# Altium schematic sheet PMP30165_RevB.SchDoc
size 431 x 279 mm; Date: Not shown in title block; ApprovedBy: Not shown in title block; CheckedBy: Not shown in title block; Author: Not shown in title block; CompanyName: Not shown in title block; Engineer: Not shown in title block; Organization: Not shown in title block; Address1: Not shown in title block; Address2: Not shown in title block; Address3: Not shown in title block; Address4: Not shown in title block; DocumentNumber: 1; Revision: Use project parameter SCH_Rev; SheetNumber: 2; SheetTotal: 3; PageSetup: Record=PageOptions¦CenterHorizontal=True¦CenterVertical=True¦PrintScale=1.00¦XCorrection=1.00¦YCorrection=1.00¦PrintKind=0¦BorderSize=5000000¦LeftOffset=0¦BottomOffset=0¦Orientation=2¦PaperLength=1000¦PaperWidth=1000¦Scale=100¦PaperSource=15¦PrintQuality=600¦MediaType=1¦DitherType=10¦PaperKind=Letter¦PrintScaleMode=1
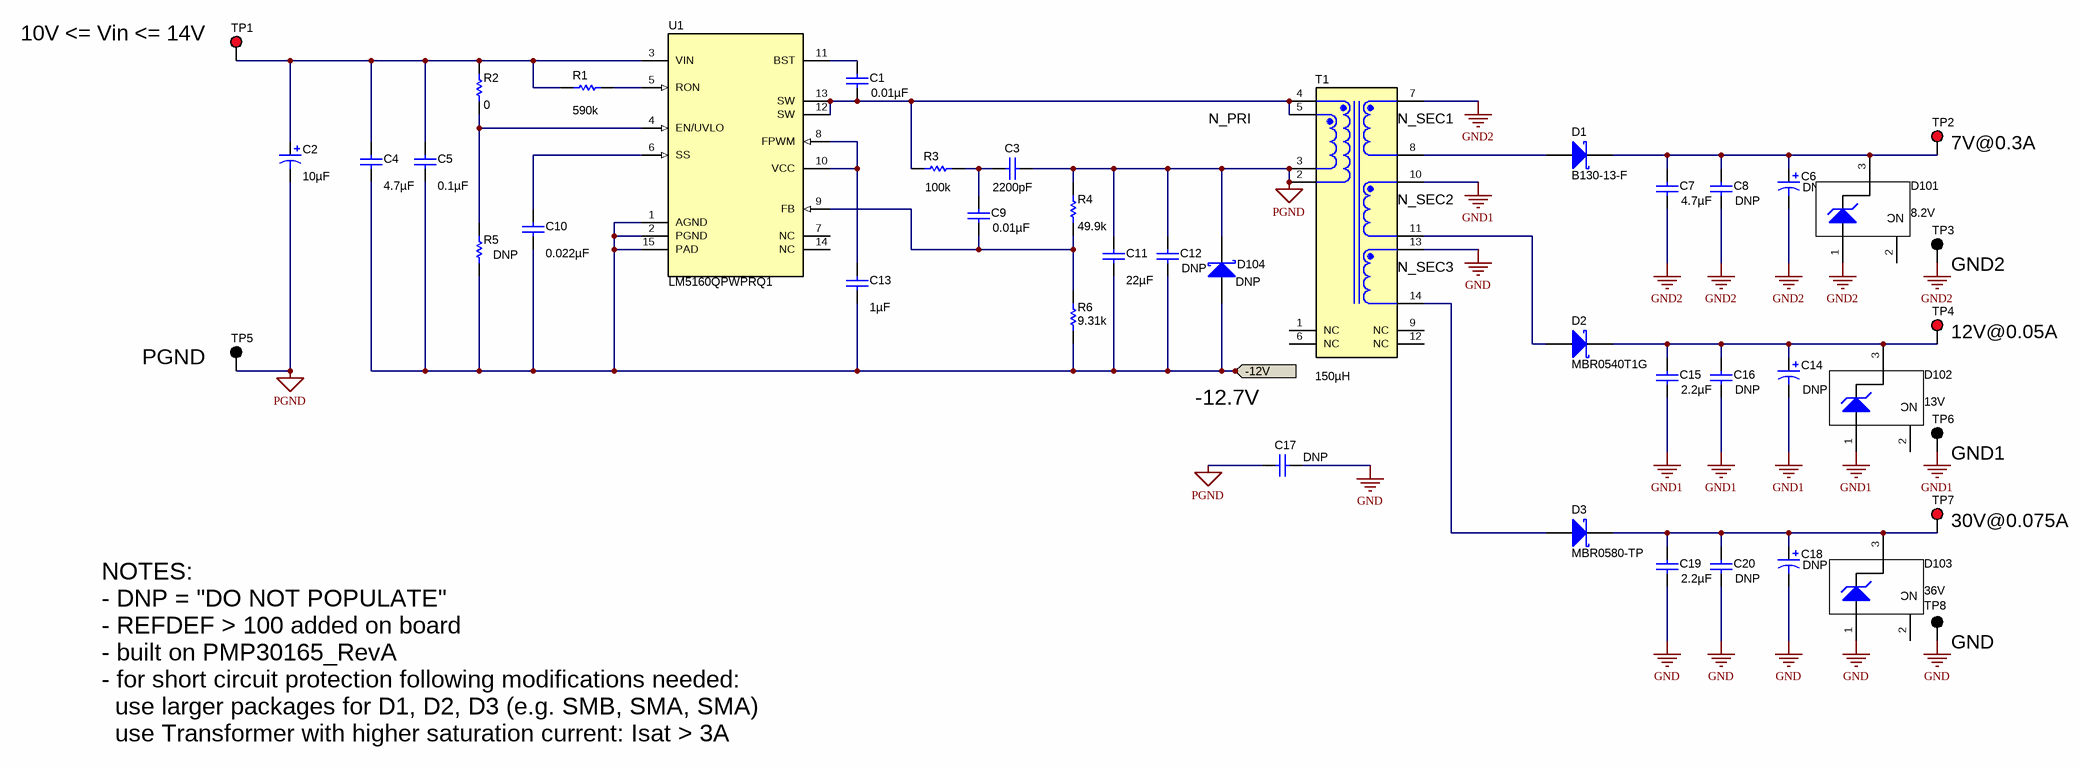
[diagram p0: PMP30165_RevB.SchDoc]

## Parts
C1  ValueDisplayed: 0.01µF  [0603]  (hidden comment: C0603C103J5RACTU)
C2  ValueDisplayed: 10µF  [SM_RADIAL_B]  (hidden comment: EEE-FK1E100R)
C3  ValueDisplayed: 2200pF  [0603]  (hidden comment: GRM188R71H222KA01D)
C4  ValueDisplayed: 4.7µF  [1206_180]  (hidden comment: C3216X7R1H475K160AC)
C5  ValueDisplayed: 0.1µF  [0603]  (hidden comment: GRM188R71H104KA93D)
C6  DNP  [SM_RADIAL_D]
C7  ValueDisplayed: 4.7µF  [1206_180]  (hidden comment: GRM31CR71C475KA01L)
C8  DNP  [1206]
C9  ValueDisplayed: 0.01µF  [0603]  (hidden comment: C0603C103J5RACTU)
C10  ValueDisplayed: 0.022µF  [0603]  (hidden comment: GRM188R71H223KA01D)
C11  ValueDisplayed: 22µF  [1210_270]  (hidden comment: GRM32ER71E226KE15L)
C12  value DNP  [1206]  (hidden comment: Used in BOM report)
C13  ValueDisplayed: 1µF  [0805_HV]  (hidden comment: 08055C105KAT2A)
C14  DNP  [SM_RADIAL_B]
C15  ValueDisplayed: 2.2µF  [1206]  (hidden comment: GRM31MR71E225KA93L)
C16  DNP  [1206]
C17  DNP  [KX_1000x700]
C18  DNP  [SM_RADIAL_D]
C19  ValueDisplayed: 2.2µF  [1206_180]  (hidden comment: GRM31CR71H225KA88L)
C20  DNP  [1206]
D1  B130-13-F  [SMA]
D2  MBR0540T1G  [SOD-123]
D3  MBR0580-TP  [SOD-123]
D101  value 8.2V  [SOT-23]  (hidden comment: BZX84B8V2LT1G)
D102  value 13V  [SOT-23]  (hidden comment: BZX84C13LT1G)
D103  value 36V  [SOT-23]  (hidden comment: BZX84C36LT1G)
D104  value DNP  [SMA]  (hidden comment: Used in BOM report)
R1  ValueDisplayed: 590k  [0603]  (hidden comment: CRCW0603590KFKEA)
R2  ValueDisplayed: 0  [0603]  (hidden comment: CRCW06030000Z0EA)
R3  ValueDisplayed: 100k  [0603]  (hidden comment: CRCW0603100KFKEA)
R4  ValueDisplayed: 49.9k  [0603]  (hidden comment: CRCW060349K9FKEA)
R5  DNP  [0603]
R6  ValueDisplayed: 9.31k  [0603]  (hidden comment: CRCW06039K31FKEA)
T1  ValueDisplayed: 150µH  [Wurth_750316586]
TP1  5000  [Keystone5000]  (value not drawn)
TP2  5000  [Keystone5000]  (value not drawn)
TP3  5001  [Keystone5001]  (value not drawn)
TP4  5000  [Keystone5000]  (value not drawn)
TP5  5001  [Keystone5001]  (value not drawn)
TP6  5001  [Keystone5001]  (value not drawn)
TP7  5000  [Keystone5000]  (value not drawn)
TP8  5001  [Keystone5001]  (value not drawn)
U1  LM5160QPWPRQ1  [PWP0014A_N]

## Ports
-12V (out)

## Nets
GND: C17.1 C18.2(-) C19.2 C20.2 D103.1(A) T1.13 TP8.1
GND1: C14.2(-) C15.2 C16.2 D102.1(A) T1.10 TP6.1
GND2: C6.2(-) C7.2 C8.2 D101.1(A) T1.7 TP3.1
PGND: C2.2(-) C3.1 C11.1 C12.1 C17.2 D104.1(K) R4.2 T1.2 T1.3 TP5.1
-12V: C4.2 C5.2 C10.2 C11.2 C12.2 C13.2 D104.2(A) R5.1 R6.1 U1.1(AGND) U1.2(PGND) U1.15(PAD) ; port -12V
NetC1_1: C1.1 U1.11(BST)
NetC1_2: C1.2 R3.1 T1.4 T1.5 U1.12(SW) U1.13(SW)
NetC2_1: C2.1(+) C4.1 C5.1 R1.1 R2.2 TP1.1 U1.3(VIN)
NetC3_2: C3.2 C9.1 R3.2
NetC6_1: C6.1(+) C7.1 C8.1 D1.1(K) D101.3(K) TP2.1
NetC9_2: C9.2 R4.1 R6.2 U1.9(FB)
NetC10_1: C10.1 U1.6(SS)
NetC13_1: C13.1 U1.8(FPWM) U1.10(VCC)
NetC14_1: C14.1(+) C15.1 C16.1 D2.1(K) D102.3(K) TP4.1
NetC18_1: C18.1(+) C19.1 C20.1 D3.1(K) D103.3(K) TP7.1
NetD1_2: D1.2(A) T1.8
NetD2_2: D2.2(A) T1.11
NetD3_2: D3.2(A) T1.14
NetR1_2: R1.2 U1.5(RON)
NetR2_1: R2.1 R5.2 U1.4(EN/UVLO)

Not connected (* = marked no-connect by the designer): D101 2(NC); D102 2(NC); D103 2(NC); T1 1(NC) 6(NC) 9(NC) 12(NC); U1 7(NC) 14(NC)

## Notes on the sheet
- (near TP1) 10V <= Vin <= 14V
- N_PRI
- (near T1) N_SEC1
- (near TP2) 7V@0.3A
- (near T1) N_SEC2
- (near T1) N_SEC3
- (near TP3) GND2
- (near TP4) 12V@0.05A
- (near TP5) PGND
- -12.7V
- (near TP6) GND1
- (near TP7) 30V@0.075A
- NOTES:
- - DNP = "DO NOT POPULATE"
- - REFDEF > 100 added on board
- - built on PMP30165_RevA
- - for short circuit protection following modifications needed:
- (near TP8) GND
- use larger packages for D1, D2, D3 (e.g. SMB, SMA, SMA)
- use Transformer with higher saturation current: Isat > 3A

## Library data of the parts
C1 C9 = C0603C103J5RACTU: CAP, CERM, 0.01 µF, 50 V, +/- 5%, X7R, 0603; Manufacturer: Kemet; Polarized: N; CompType: Capacitor; Value: 0.01uF; U/M: EA; Cap_F: 0.00000001; Tolerance_%: 5; Value1: Unknown; VDC_V: 50; Value2: 50V; TaMin_C: -55; TaMax_C: 125; SizeArea_mm2: 1.28; SizeAreaWB_mm2: 4.68; SizeX_mm: 1.6; SizeY_mm: 0.8; SizeZ_mm: 1; AEC Category: Q200
C2 = EEE-FK1E100R: CAP, AL, 10 µF, 25 V, +/- 20%, 1.35 ohm, AEC-Q200 Grade 2, SMD; Manufacturer: Panasonic; Polarized: Y; CompType: Capacitor; Value: 10uF; U/M: EA; Cap_F: 0.00001; Tolerance_%: 20; VDC_V: 25; Value2: 25V; ESR_ohm: 1.35; IRMS_A: 0.09; TaMin_C: -55; TaMax_C: 105; Cap_Case: B; SizeAreaWB_mm2: 47.25; SizeArea_mm2: 23.65; SizeX_mm: 5.5; SizeY_mm: 4.3; SizeZ_mm: 5.4; AEC Category: Q200; AEC Grade: 2
C3 = GRM188R71H222KA01D: CAP, CERM, 2200 pF, 50 V, +/- 10%, X7R, 0603; Manufacturer: MuRata; Polarized: N; CompType: Capacitor; Value: 2200pF; U/M: EA; Cap_F: 0.0000000022; Tolerance_%: 10; Value1: Unknown; VDC_V: 50; Value2: 50V; TaMin_C: -55; TaMax_C: 125; SizeArea_mm2: 1.28; SizeAreaWB_mm2: 4.68; SizeX_mm: 1.6; SizeY_mm: 0.8; SizeZ_mm: 1; AEC Category: Q200
C4 = C3216X7R1H475K160AC: CAP, CERM, 4.7 µF, 50 V, +/- 10%, X7R, 1206; Manufacturer: TDK; Polarized: N; CompType: Capacitor; Value: 4.7uF; U/M: EA; Cap_F: 0.0000047; Tolerance_%: 10; ESR_ohm: 0.003158; Value1: 0.003158 ohm; VDC_V: 50; Value2: 50V; IRMS_A: 4.08379; TaMin_C: -55; TaMax_C: 125; SizeArea_mm2: 5.12; SizeAreaWB_mm2: 10.92; SizeX_mm: 3.2; SizeY_mm: 1.6; SizeZ_mm: 1.8; AEC Category: Q200
C5 = GRM188R71H104KA93D: CAP, CERM, 0.1 µF, 50 V, +/- 10%, X7R, 0603; Manufacturer: MuRata; Polarized: N; CompType: Capacitor; Value: 0.1uF; U/M: EA; Cap_F: 0.0000001; Tolerance_%: 10; Value1: Unknown; VDC_V: 50; Value2: 50V; TaMin_C: -55; TaMax_C: 125; SizeArea_mm2: 1.28; SizeAreaWB_mm2: 4.68; SizeX_mm: 1.6; SizeY_mm: 0.8; SizeZ_mm: 1; AEC Category: Q200
C6 = EEE-FK1C470P: CAP, AL, 47 µF, 16 V, +/- 20%, 0.36 ohm, AEC-Q200 Grade 2, SMD; Manufacturer: Panasonic; Polarized: Y; CompType: Capacitor; U/M: EA; Cap_F: 0.000047; Tolerance_%: 20; VDC_V: 16; Value2: 16V; ESR_ohm: 0.36; IRMS_A: 0.24; TaMin_C: -55; TaMax_C: 105; Cap_Case: D; SizeAreaWB_mm2: 84.28; SizeArea_mm2: 51.48; SizeX_mm: 7.8; SizeY_mm: 6.6; SizeZ_mm: 5.4; AEC Category: Q200; AEC Grade: 2
C7 = GRM31CR71C475KA01L: CAP, CERM, 4.7 µF, 16 V, +/- 10%, X7R, 1206; Manufacturer: MuRata; Polarized: N; CompType: Capacitor; Value: 4.7uF; U/M: EA; Cap_F: 0.0000047; Tolerance_%: 10; Value1: Unknown; VDC_V: 16; Value2: 16V; TaMin_C: -55; TaMax_C: 125; Cap_Case: 1210; SizeArea_mm2: 5.12; SizeAreaWB_mm2: 10.92; SizeX_mm: 3.2; SizeY_mm: 1.6; SizeZ_mm: 1.8; AEC Category: Q200
C8 C16 C20 = Capacitor: CAP, CERM, xxxF, xxV, [TempCo], xx%, [PackageReference]; Manufacturer: Used in BOM report; Polarized: N; U/M: EA
C10 = GRM188R71H223KA01D: CAP, CERM, 0.022 µF, 50 V, +/- 10%, X7R, 0603; Manufacturer: MuRata; Polarized: N; CompType: Capacitor; Value: 0.022uF; U/M: EA; Cap_F: 0.000000022; Tolerance_%: 10; Value1: Unknown; VDC_V: 50; Value2: 50V; TaMin_C: -55; TaMax_C: 125; SizeArea_mm2: 1.28; SizeAreaWB_mm2: 4.68; SizeX_mm: 1.6; SizeY_mm: 0.8; SizeZ_mm: 1; AEC Category: Q200
C11 = GRM32ER71E226KE15L: CAP, CERM, 22 µF, 25 V, +/- 10%, X7R, 1210; Manufacturer: MuRata; Polarized: N; CompType: Capacitor; Value: 22uF; U/M: EA; Cap_F: 0.000022; Tolerance_%: 10; Value1: Unknown; VDC_V: 25; Value2: 25V; TaMin_C: -55; TaMax_C: 125; Cap_Case: 1210; SizeArea_mm2: 8; SizeAreaWB_mm2: 14.7; SizeX_mm: 3.2; SizeY_mm: 2.5; SizeZ_mm: 2.7; AEC Category: Q200
C12 = Capacitor: CAP, CERM, xxxF, xxV, [TempCo], xx%, [PackageReference]; Polarized: N; U/M: EA
C13 = 08055C105KAT2A: CAP, CERM, 1 µF, 50 V, +/- 10%, X7R, 0805; Manufacturer: AVX; Polarized: N; CompType: Capacitor; Value: 1uF; U/M: EA; Cap_F: 0.000001; Tolerance_%: 10; Value1: Unknown; VDC_V: 50; Value2: 50V; TaMin_C: -55; TaMax_C: 125; Cap_Case: 0805; SizeArea_mm2: 2.5; SizeAreaWB_mm2: 6.75; SizeX_mm: 2; SizeY_mm: 1.25; SizeZ_mm: 1.45; AEC Category: Q200
C14 = EEE-FK1E100R: CAP, AL, 10 µF, 25 V, +/- 20%, 1.35 ohm, AEC-Q200 Grade 2, SMD; Manufacturer: Panasonic; Polarized: Y; CompType: Capacitor; ValueDisplayed: 10µF; U/M: EA; Cap_F: 0.00001; Tolerance_%: 20; VDC_V: 25; Value2: 25V; ESR_ohm: 1.35; IRMS_A: 0.09; TaMin_C: -55; TaMax_C: 105; Cap_Case: B; SizeAreaWB_mm2: 47.25; SizeArea_mm2: 23.65; SizeX_mm: 5.5; SizeY_mm: 4.3; SizeZ_mm: 5.4; AEC Category: Q200; AEC Grade: 2
C15 = GRM31MR71E225KA93L: CAP, CERM, 2.2 µF, 25 V, +/- 10%, X7R, 1206; Manufacturer: MuRata; Polarized: N; CompType: Capacitor; Value: 2.2uF; U/M: EA; Cap_F: 0.0000022; Tolerance_%: 10; Value1: Unknown; VDC_V: 25; Value2: 25V; TaMin_C: -55; TaMax_C: 125; Cap_Case: 1210; SizeArea_mm2: 5.12; SizeAreaWB_mm2: 10.92; SizeX_mm: 3.2; SizeY_mm: 1.6; SizeZ_mm: 1.35; AEC Category: Q200
C17 = DE1E3KX332MN4AP01F: CAP, CERM, 3300 pF, 300 V, +/- 20%, E, D10xT7mm; Manufacturer: MuRata; Polarized: N; CompType: Capacitor; U/M: EA; Cap_F: 0.0000000033; Tolerance_%: 20; Value1: Unknown; VDC_V: 300; Value2: 300V; TaMin_C: -40; TaMax_C: 125; Cap_Case: 10x7mm; SizeArea_mm2: 70; SizeAreaWB_mm2: 108; SizeX_mm: 10; SizeY_mm: 7; SizeZ_mm: 13; AEC Category: Q200
C18 = EEE-FK1H100P: CAP, AL, 10 µF, 50 V, +/- 20%, 0.88 ohm, AEC-Q200 Grade 2, SMD; Manufacturer: Panasonic; Polarized: Y; CompType: Capacitor; U/M: EA; Cap_F: 0.00001; Tolerance_%: 20; VDC_V: 50; Value2: 50V; ESR_ohm: 0.88; IRMS_A: 0.165; TaMin_C: -55; TaMax_C: 105; Cap_Case: D; SizeAreaWB_mm2: 84.28; SizeArea_mm2: 51.48; SizeX_mm: 7.8; SizeY_mm: 6.6; SizeZ_mm: 5.4; AEC Category: Q200; AEC Grade: 2
C19 = GRM31CR71H225KA88L: CAP, CERM, 2.2 µF, 50 V, +/- 10%, X7R, 1206; Manufacturer: MuRata; Polarized: N; CompType: Capacitor; Value: 2.2uF; U/M: EA; Cap_F: 0.0000022; Tolerance_%: 10; Value1: Unknown; VDC_V: 50; Value2: 50V; TaMin_C: -55; TaMax_C: 125; Cap_Case: 1206; SizeArea_mm2: 5.12; SizeAreaWB_mm2: 10.92; SizeX_mm: 3.2; SizeY_mm: 1.6; SizeZ_mm: 1.8; AEC Category: Q200
D1 = B130-13-F: Diode, Schottky, 30 V, 1 A, SMA; Manufacturer: Diodes Inc.; U/M: EA; Vf_V: 0.5; Value: 30V; Value1: 1A; Value2: 0.5V; Io_A: 1; Vr_V: 30; TJmax_C: 150; RJC_CperW: 20; SizeAreaWB_mm2: 37.3428; SizeArea_mm2: 16.3228; SizeX_mm: 5.59; SizeY_mm: 2.92; SizeZ_mm: 2.87; AEC Category: Q101
D2 = MBR0540T1G: Diode, Schottky, 40 V, 0.5 A, SOD-123; Manufacturer: ON Semiconductor; U/M: EA; Vf_V: 0.51; Value: 40V; Value1: 0.5A; Value2: 0.51V; Io_A: 0.5; Vr_V: 40; TJmax_C: 150; RJC_CperW: 118; SizeAreaWB_mm2: 13.095; SizeArea_mm2: 6.545; SizeX_mm: 3.85; SizeY_mm: 1.7; SizeZ_mm: 1.35; AEC Category: Q101
D3 = MBR0580-TP: Diode, Schottky, 80 V, 0.5 A, SOD-123; Manufacturer: Micro Commercial Components; U/M: EA; Vf_V: 0.8; Value: 80V; Value1: 0.5A; Value2: 0.8V; Io_A: 0.5; Vr_V: 80; TJmax_C: 150; SizeAreaWB_mm2: 13.095; SizeArea_mm2: 6.545; SizeX_mm: 3.85; SizeY_mm: 1.7; SizeZ_mm: 1.35; AEC Category: Q101
D101 = BZX84B8V2LT1G: Diode, Zener, 8.2 V, 225 mW, SOT-23; Manufacturer: ON Semiconductor; U/M: EA; Power_W: 0.225; Vz_V: 8.2; Value1: 0.225W; RJA_CperW: 556; SizeAreaWB_mm2: 14; SizeArea_mm2: 7.5; SizeX_mm: 2.5; SizeY_mm: 3; SizeZ_mm: 1.1; AEC Category: Q101
D102 = BZX84C13LT1G: Diode, Zener, 13 V, 225 mW, SOT-23; Manufacturer: ON Semiconductor; U/M: EA; Power_W: 0.225; Vz_V: 13; Value1: 0.225W; RJA_CperW: 556; SizeAreaWB_mm2: 14; SizeArea_mm2: 7.5; SizeX_mm: 2.5; SizeY_mm: 3; SizeZ_mm: 1.1; AEC Category: Q101
D103 = BZX84C36LT1G: Diode, Zener, 36 V, 225 mW, SOT-23; Manufacturer: ON Semiconductor; U/M: EA; Power_W: 0.225; Vz_V: 36; Value1: 0.225W; RJA_CperW: 556; SizeAreaWB_mm2: 14; SizeArea_mm2: 7.5; SizeX_mm: 2.5; SizeY_mm: 3; SizeZ_mm: 1.1; AEC Category: Q101
D104 = Diode_Schottky: Diode, Schottky, xxV, xxA, [PackageReference]; U/M: EA
R1 = CRCW0603590KFKEA: RES, 590 k, 1%, 0.1 W, 0603; Manufacturer: Vishay-Dale; CompType: Resistor; Value: 590k; Res_ohm: 590000; Tolerance_%: 1; Power_W: 0.1; Value2: 0.1W; VDC_V: 75; TempCo: 100 ppm/C; SizeArea_mm2: 1.28; SizeX_mm: 1.6; SizeY_mm: 0.8; EIA_Code: E96; U/M: EA; AEC Category: Q200
R2 = CRCW06030000Z0EA: RES, 0, 5%, 0.1 W, 0603; Manufacturer: Vishay-Dale; CompType: Resistor; Value: 0; Value_Code: 0000; Tolerance_%: 5; Power_W: 0.1; Value2: 0.1W; VDC_V: 75; TempCo: 200 ppm/C; SizeArea_mm2: 1.28; SizeX_mm: 1.6; SizeY_mm: 0.8; SizeZ_mm: 1; EIA_Code: E24; U/M: EA; AEC Category: Q200
R3 = CRCW0603100KFKEA: RES, 100 k, 1%, 0.1 W, 0603; Manufacturer: Vishay-Dale; CompType: Resistor; Value: 100k; Res_ohm: 100000; Tolerance_%: 1; Power_W: 0.1; Value2: 0.1W; VDC_V: 75; TempCo: 100 ppm/C; SizeArea_mm2: 1.28; SizeX_mm: 1.6; SizeY_mm: 0.8; EIA_Code: E96; U/M: EA; AEC Category: Q200
R4 = CRCW060349K9FKEA: RES, 49.9 k, 1%, 0.1 W, 0603; Manufacturer: Vishay-Dale; CompType: Resistor; Value: 49.9k; Res_ohm: 49900; Value_Code: 49k9; Tolerance_%: 1; Power_W: 0.1; Value2: 0.1W; VDC_V: 75; TempCo: 100 ppm/C; SizeArea_mm2: 1.28; SizeX_mm: 1.6; SizeY_mm: 0.8; EIA_Code: E96; U/M: EA; AEC Category: Q200
R5 = Resistor: RES, xxx ohm, x%, xW, [PackageReference]; Manufacturer: Used in BOM report; U/M: EA
R6 = CRCW06039K31FKEA: RES, 9.31 k, 1%, 0.1 W, 0603; Manufacturer: Vishay-Dale; CompType: Resistor; Value: 9.31k; Res_ohm: 9310; Value_Code: 9k31; Tolerance_%: 1; Power_W: 0.1; Value2: 0.1W; VDC_V: 75; TempCo: 100 ppm/C; SizeArea_mm2: 1.28; SizeX_mm: 1.6; SizeY_mm: 0.8; EIA_Code: E96; U/M: EA; AEC Category: Q200
T1 = 750316586: Transformer, 150 uH, TH; Manufacturer: Wurth Elektronik; SymbolCreator: Altium; Value: 150uH; Lp: 150; DCR_ohm: 0.094; Ns1toNp: 0.592; Ns2toNp: 1; Ns3toNp: 2.41; Rs1: 0.1; Rs2: 0.47; Rs3: 1.25; SizeAreaWB_mm2: 653.4; SizeArea_mm2: 555; SizeX_mm: 25; SizeY_mm: 22.2; SizeZ_mm: 16
TP1 TP2 TP4 TP7 = 5000: Test Point, Miniature, Red, TH; Manufacturer: Keystone; CompType: Test Point Loop; ContactFinish: Silver
TP3 TP5 TP6 TP8 = 5001: Test Point, Miniature, Black, TH; Manufacturer: Keystone; CompType: Test Point Loop; ContactFinish: Silver
U1 = LM5160QPWPRQ1: Wide Input 65-V, 1.5-A Synchronous Buck / Fly-Buck Converter, PWP0014A; Alternate PartNumber: LM5160QPWPTQ1; Manufacturer: Texas Instruments; SymbolCreator: a0411947; SizeArea_mm2: 32; SizeAreaWB_mm2: 58.8; SizeX_mm: 6.4; SizeY_mm: 5; SizeZ_mm: 1.2; CompType: IC; U/M: EA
